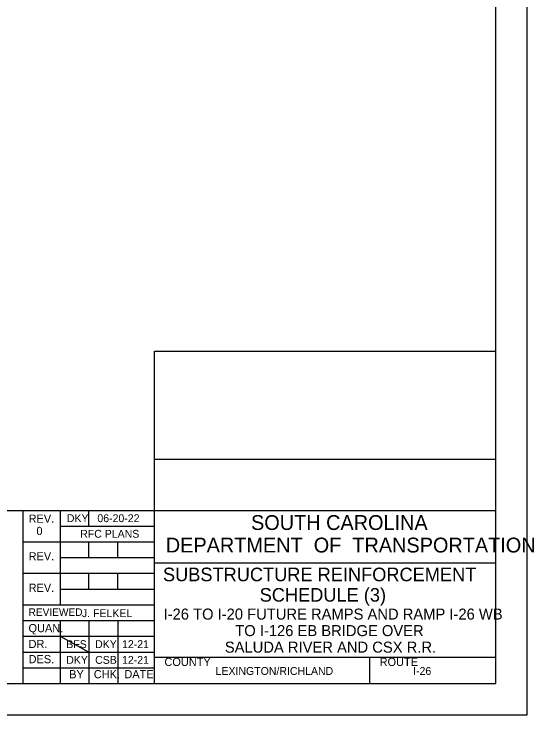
# Model space of a CAD drawing. Extents: x -121.2 to -24.9, y 6.4 to 65.7.
# Drawn here: x -46.89 to -24.88, y 6.35 to 36.04 of the extents above; entities that cross this region are included whole.
import ezdxf

# ---------------------------------------------------------------- set-up
doc = ezdxf.new("R2010")
doc.units = 0
for name, color, linetype in [('BR_BORDER LINES', 7, 'Continuous'), ('BR_TEXT', 7, 'Continuous'), ('Level 31', 7, 'Continuous')]:
    doc.layers.add(name, color=color, linetype=linetype)

msp = doc.modelspace()

# ---------------------------------------------------------------- linework, layer by layer
at = {"layer": 'BR_BORDER LINES'}
for p, q in [((-26.496, 7.683), (-26.496, 63.683)), ((-40.941, 7.683), (-40.941, 21.754)), ((-40.941, 21.754), (-26.496, 21.754)), ((-40.94, 17.182), (-26.496, 17.182)), ((-60.804, 15.017), (-46.496, 15.017)), ((-46.496, 7.683), (-46.496, 15.017)), ((-46.496, 15.017), (-26.496, 15.017)), ((-44.941, 15.017), (-44.941, 11.017)), ((-43.718, 14.35), (-43.718, 15.017)), ((-44.941, 14.35), (-40.941, 14.35)), ((-46.496, 13.684), (-40.941, 13.684)), ((-43.718, 13.017), (-43.718, 13.684)), ((-42.496, 13.017), (-42.496, 13.684)), ((-44.941, 13.017), (-40.941, 13.017)), ((-40.941, 12.795), (-40.941, 12.795)), ((-40.941, 12.795), (-26.495, 12.795)), ((-46.496, 12.35), (-40.941, 12.35)), ((-43.718, 11.684), (-43.718, 12.35)), ((-42.496, 11.684), (-42.496, 12.35)), ((-44.941, 11.684), (-40.941, 11.684)), ((-46.496, 11.017), (-40.941, 11.017)), ((-46.496, 10.35), (-40.941, 10.35)), ((-44.941, 10.35), (-44.941, 7.683)), ((-43.718, 10.35), (-43.718, 7.683)), ((-42.496, 10.35), (-42.496, 7.683)), ((-46.496, 9.683), (-40.941, 9.683)), ((-46.496, 9.017), (-40.941, 9.017)), ((-40.941, 8.795), (-26.496, 8.795)), ((-40.68, 8.795), (-26.496, 8.795)), ((-31.829, 7.683), (-31.829, 8.795)), ((-46.496, 8.35), (-40.941, 8.35)), ((-116.272, 7.683), (-26.496, 7.683))]:
    msp.add_line(p, q, dxfattribs=at)
at = {"layer": 'Level 31'}
for p, q in [((-33.717, 11.621), (-33.717, 11.621)), ((-44.941, 9.683), (-43.718, 9.017))]:
    msp.add_line(p, q, dxfattribs=at)
msp.add_lwpolyline([(-121.161, 6.35), (-25.161, 6.35), (-25.161, 65.017), (-121.161, 65.017)], close=True, dxfattribs=at)

# ---------------------------------------------------------------- texts
at = {"layer": 'BR_TEXT'}
for s, height, p in [('DKY', 0.3333, (-44.652, 14.517)), ('06-20-22', 0.3333, (-43.36, 14.517)), ('REV.', 0.3467, (-46.27, 14.491)), ('SOUTH CAROLINA', 0.62899, (-36.855, 14.186)), ('0', 0.347, (-45.94, 13.971)), ('RFC PLANS', 0.3333, (-44.087, 13.857)), ('DEPARTMENT  OF  TRANSPORTATION', 0.62899, (-40.463, 13.232)), ('REV.', 0.3467, (-46.27, 12.898)), ('SUBSTRUCTURE REINFORCEMENT', 0.576, (-40.583, 12.014)), ('REV.', 0.3467, (-46.27, 11.565)), ('SCHEDULE (3)', 0.576, (-36.489, 11.15)), ('REVIEWED', 0.32, (-46.272, 10.546)), ('J. FELKEL', 0.3333, (-44.015, 10.495)), ('I-26 TO I-20 FUTURE RAMPS AND RAMP I-26 WB', 0.46667, (-40.558, 10.39)), ('QUAN.', 0.3467, (-46.274, 9.857)), ('TO I-126 EB BRIDGE OVER', 0.46667, (-37.523, 9.69)), ('DR.', 0.3467, (-46.273, 9.186)), ('BFS', 0.3333, (-44.677, 9.183)), ('DKY', 0.3333, (-43.456, 9.183)), ('12-21', 0.3333, (-42.316, 9.183)), ('SALUDA RIVER AND CSX R.R.', 0.46667, (-37.965, 8.99)), ('DES.', 0.3467, (-46.271, 8.543)), ('DKY', 0.3333, (-44.679, 8.517)), ('CSB', 0.3333, (-43.454, 8.517)), ('12-21', 0.3333, (-42.316, 8.517)), ('COUNTY', 0.3467, (-40.521, 8.425)), ('ROUTE', 0.3467, (-31.41, 8.425)), ('LEXINGTON/RICHLAND', 0.33332, (-38.355, 8.047)), ('I-26', 0.3333, (-29.993, 8.047)), ('BY', 0.3467, (-44.553, 7.902)), ('CHK.', 0.3467, (-43.511, 7.906)), ('DATE', 0.3467, (-42.217, 7.906))]:
    msp.add_text(s, height=height, dxfattribs=at).set_placement(p)

doc.saveas('drawing.dxf')
